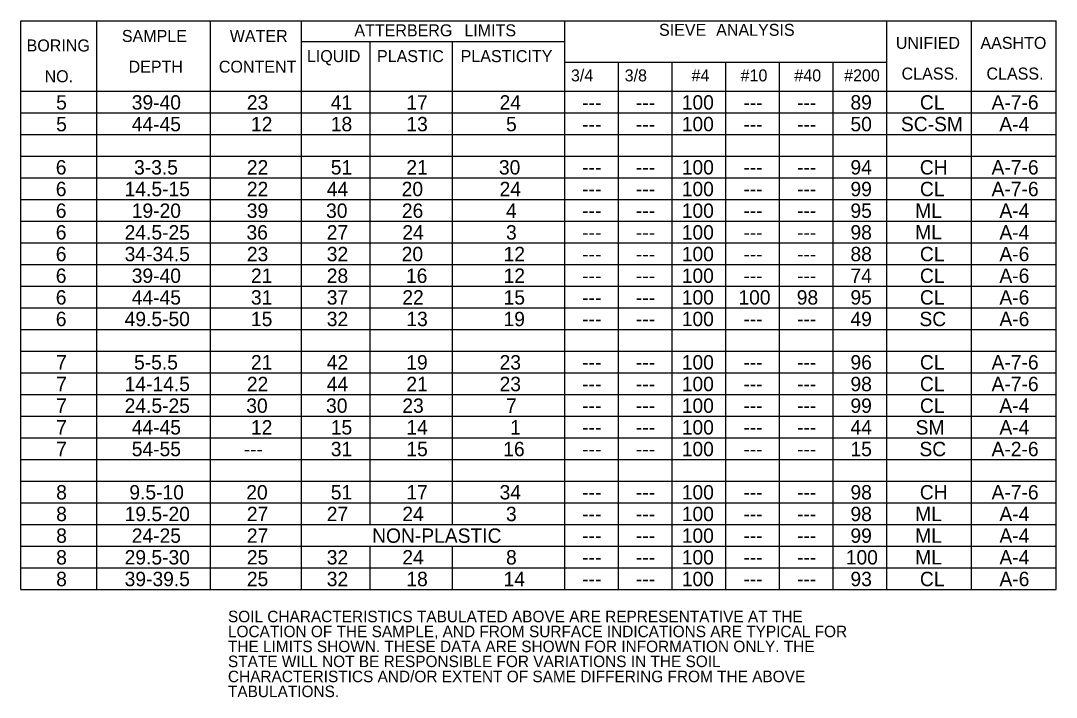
# Model space of a CAD drawing. Extents: x 1197542 to 1207464, y 185022 to 237324.
# Drawn here: x 1206798.9 to 1206906.8, y 185052.2 to 185122.8 of the extents above; entities that cross this region are included whole.
import ezdxf

# ---------------------------------------------------------------- set-up
doc = ezdxf.new("R2010")
doc.units = 0
doc.layers.add('R_No Plot', color=7, linetype='Continuous')

msp = doc.modelspace()

# ---------------------------------------------------------------- linework, layer by layer
at = {"layer": 'R_No Plot'}
for p, q in [((1206798.86, 185122.77), (1206798.86, 185122.77)), ((1206798.86, 185122.77), (1206906.83, 185122.77)), ((1206798.86, 185063.47), (1206798.86, 185122.77)), ((1206806.8, 185063.47), (1206806.8, 185122.77)), ((1206818.64, 185063.47), (1206818.64, 185122.77)), ((1206828.14, 185063.47), (1206828.14, 185122.77)), ((1206855.58, 185063.47), (1206855.58, 185122.77)), ((1206889.16, 185063.47), (1206889.16, 185122.77)), ((1206898, 185063.47), (1206898, 185122.77)), ((1206906.83, 185063.47), (1206906.83, 185122.77)), ((1206828.14, 185120.6), (1206855.58, 185120.6)), ((1206835.3, 185070.25), (1206835.3, 185120.6)), ((1206843.88, 185070.25), (1206843.88, 185120.6)), ((1206855.58, 185118.44), (1206889.16, 185118.44)), ((1206861.17, 185063.47), (1206861.17, 185118.44)), ((1206866.77, 185063.47), (1206866.77, 185118.44)), ((1206872.37, 185063.47), (1206872.37, 185118.44)), ((1206877.97, 185063.47), (1206877.97, 185118.44)), ((1206883.57, 185063.47), (1206883.57, 185118.44)), ((1206798.86, 185115.42), (1206906.83, 185115.42)), ((1206889.16, 185115.42), (1206906.83, 185115.42)), ((1206798.86, 185113.16), (1206906.83, 185113.16)), ((1206798.86, 185110.9), (1206906.83, 185110.9)), ((1206798.86, 185108.64), (1206906.83, 185108.64)), ((1206798.86, 185106.39), (1206906.83, 185106.39)), ((1206798.86, 185104.13), (1206906.83, 185104.13)), ((1206798.86, 185101.87), (1206906.83, 185101.87)), ((1206798.86, 185099.61), (1206906.83, 185099.61)), ((1206798.86, 185097.35), (1206906.83, 185097.35)), ((1206798.86, 185095.09), (1206906.83, 185095.09)), ((1206798.86, 185092.83), (1206906.83, 185092.83)), ((1206798.86, 185090.57), (1206906.83, 185090.57)), ((1206798.86, 185088.32), (1206906.83, 185088.32)), ((1206798.86, 185086.06), (1206906.83, 185086.06)), ((1206798.86, 185083.8), (1206906.83, 185083.8)), ((1206798.86, 185081.54), (1206906.83, 185081.54)), ((1206798.86, 185079.28), (1206906.83, 185079.28)), ((1206798.86, 185077.02), (1206906.83, 185077.02)), ((1206798.86, 185074.76), (1206906.83, 185074.76)), ((1206798.86, 185072.5), (1206906.83, 185072.5)), ((1206798.86, 185070.25), (1206906.83, 185070.25)), ((1206798.86, 185067.99), (1206906.83, 185067.99)), ((1206835.3, 185063.47), (1206835.3, 185067.99)), ((1206843.88, 185063.47), (1206843.88, 185067.99)), ((1206798.86, 185065.73), (1206906.83, 185065.73)), ((1206798.86, 185063.47), (1206906.83, 185063.47))]:
    msp.add_line(p, q, dxfattribs=at)

# ---------------------------------------------------------------- texts
for s, height, p in [('ATTERBERG', 1.25, (1206833.65, 185121.14)), ('LIMITS', 1.25, (1206845.12, 185121.14)), ('SIEVE', 1.25, (1206865.41, 185121.19)), ('ANALYSIS', 1.25, (1206871.37, 185121.19)), ('SAMPLE', 1.25, (1206809.41, 185120.55)), ('WATER', 1.25, (1206820.66, 185120.55)), ('BORING', 1.25, (1206799.48, 185119.56)), ('UNIFIED', 1.25, (1206890.1, 185119.83)), ('AASHTO', 1.25, (1206898.92, 185119.83)), ('LIQUID', 1.25, (1206828.7, 185118.45)), ('PLASTIC', 1.25, (1206836.01, 185118.45)), ('PLASTICITY', 1.25, (1206844.73, 185118.45)), ('DEPTH', 1.25, (1206810.11, 185117.35)), ('CONTENT', 1.25, (1206819.52, 185117.35)), ('CLASS.', 1.25, (1206890.7, 185116.63)), ('CLASS.', 1.25, (1206899.55, 185116.63)), ('NO.', 1.25, (1206801.35, 185116.35)), ('3/4', 1.25, (1206856.23, 185116.44)), ('3/8', 1.25, (1206861.83, 185116.44)), ('#4', 1.25, (1206868.8, 185116.44)), ('#10', 1.25, (1206873.92, 185116.44)), ('#40', 1.25, (1206879.52, 185116.44)), ('#200', 1.25, (1206884.71, 185116.44)), ('5', 1.5, (1206802.56, 185113.5)), ('39-40', 1.5, (1206810.44, 185113.5)), ('23', 1.5, (1206822.44, 185113.5)), ('41', 1.5, (1206831.19, 185113.5)), ('17', 1.5, (1206839.07, 185113.5)), ('24', 1.5, (1206848.79, 185113.5)), ('100', 1.5, (1206867.78, 185113.5)), ('89', 1.5, (1206885.37, 185113.5)), ('CL', 1.5, (1206892.61, 185113.5)), ('A-7-6', 1.5, (1206900.08, 185113.5)), ('---', 1.5, (1206857.4, 185113.5)), ('---', 1.5, (1206863, 185113.5)), ('---', 1.5, (1206874.2, 185113.5)), ('---', 1.5, (1206879.8, 185113.5)), ('5', 1.5, (1206802.56, 185111.24)), ('44-45', 1.5, (1206810.44, 185111.24)), ('12', 1.5, (1206822.87, 185111.24)), ('18', 1.5, (1206831.19, 185111.24)), ('13', 1.5, (1206839.07, 185111.24)), ('5', 1.5, (1206849.46, 185111.24)), ('100', 1.5, (1206867.78, 185111.24)), ('50', 1.5, (1206885.37, 185111.24)), ('SC-SM', 1.5, (1206890.63, 185111.24)), ('A-4', 1.5, (1206900.89, 185111.24)), ('---', 1.5, (1206857.4, 185111.24)), ('---', 1.5, (1206863, 185111.24)), ('---', 1.5, (1206874.2, 185111.24)), ('---', 1.5, (1206879.8, 185111.24)), ('6', 1.5, (1206802.52, 185106.73)), ('3-3.5', 1.5, (1206810.68, 185106.73)), ('22', 1.5, (1206822.44, 185106.73)), ('51', 1.5, (1206831.19, 185106.73)), ('21', 1.5, (1206839.07, 185106.73)), ('30', 1.5, (1206848.72, 185106.73)), ('100', 1.5, (1206867.78, 185106.73)), ('94', 1.5, (1206885.37, 185106.73)), ('CH', 1.5, (1206892.6, 185106.73)), ('A-7-6', 1.5, (1206900.08, 185106.73)), ('---', 1.5, (1206857.4, 185106.73)), ('---', 1.5, (1206863, 185106.73)), ('---', 1.5, (1206874.2, 185106.73)), ('---', 1.5, (1206879.8, 185106.73)), ('6', 1.5, (1206802.52, 185104.47)), ('14.5-15', 1.5, (1206809.7, 185104.47)), ('22', 1.5, (1206822.44, 185104.47)), ('44', 1.5, (1206830.77, 185104.47)), ('20', 1.5, (1206838.58, 185104.47)), ('24', 1.5, (1206848.79, 185104.47)), ('---', 1.5, (1206857.4, 185104.47)), ('---', 1.5, (1206863, 185104.47)), ('100', 1.5, (1206867.78, 185104.47)), ('---', 1.5, (1206874.2, 185104.47)), ('---', 1.5, (1206879.8, 185104.47)), ('99', 1.5, (1206885.37, 185104.47)), ('CL', 1.5, (1206892.61, 185104.47)), ('A-7-6', 1.5, (1206900.08, 185104.47)), ('6', 1.5, (1206802.52, 185102.21)), ('19-20', 1.5, (1206810.44, 185102.21)), ('39', 1.5, (1206822.43, 185102.21)), ('30', 1.5, (1206830.7, 185102.21)), ('26', 1.5, (1206838.6, 185102.21)), ('4', 1.5, (1206849.46, 185102.21)), ('---', 1.5, (1206857.4, 185102.21)), ('---', 1.5, (1206863, 185102.21)), ('100', 1.5, (1206867.78, 185102.21)), ('---', 1.5, (1206874.2, 185102.21)), ('---', 1.5, (1206879.8, 185102.21)), ('95', 1.5, (1206885.37, 185102.21)), ('ML', 1.5, (1206892.12, 185102.21)), ('A-4', 1.5, (1206900.9, 185102.21)), ('6', 1.5, (1206802.52, 185099.95)), ('24.5-25', 1.5, (1206809.7, 185099.95)), ('36', 1.5, (1206822.4, 185099.95)), ('27', 1.5, (1206830.77, 185099.95)), ('24', 1.5, (1206838.65, 185099.95)), ('3', 1.5, (1206849.46, 185099.95)), ('---', 1.5, (1206857.4, 185099.95)), ('---', 1.5, (1206863, 185099.95)), ('100', 1.5, (1206867.78, 185099.95)), ('---', 1.5, (1206874.2, 185099.95)), ('---', 1.5, (1206879.8, 185099.95)), ('98', 1.5, (1206885.37, 185099.95)), ('ML', 1.5, (1206892.12, 185099.97)), ('A-4', 1.5, (1206900.9, 185099.95)), ('6', 1.5, (1206802.52, 185097.69)), ('34-34.5', 1.5, (1206809.7, 185097.69)), ('23', 1.5, (1206822.44, 185097.69)), ('32', 1.5, (1206830.77, 185097.69)), ('20', 1.5, (1206838.58, 185097.69)), ('12', 1.5, (1206849.21, 185097.69)), ('100', 1.5, (1206867.78, 185097.69)), ('88', 1.5, (1206885.37, 185097.69)), ('CL', 1.5, (1206892.61, 185097.69)), ('A-6', 1.5, (1206900.9, 185097.69)), ('---', 1.5, (1206857.4, 185097.69)), ('---', 1.5, (1206863, 185097.69)), ('---', 1.5, (1206874.2, 185097.69)), ('---', 1.5, (1206879.8, 185097.69)), ('6', 1.5, (1206802.52, 185095.43)), ('39-40', 1.5, (1206810.44, 185095.43)), ('21', 1.5, (1206822.87, 185095.43)), ('28', 1.5, (1206830.77, 185095.43)), ('16', 1.5, (1206839.03, 185095.43)), ('12', 1.5, (1206849.21, 185095.43)), ('100', 1.5, (1206867.78, 185095.43)), ('74', 1.5, (1206885.37, 185095.43)), ('CL', 1.5, (1206892.61, 185095.43)), ('A-6', 1.5, (1206900.9, 185095.43)), ('---', 1.5, (1206857.4, 185095.43)), ('---', 1.5, (1206863, 185095.43)), ('---', 1.5, (1206874.2, 185095.43)), ('---', 1.5, (1206879.8, 185095.43)), ('6', 1.5, (1206802.52, 185093.17)), ('44-45', 1.5, (1206810.44, 185093.17)), ('31', 1.5, (1206822.87, 185093.17)), ('37', 1.5, (1206830.77, 185093.17)), ('22', 1.5, (1206838.65, 185093.17)), ('15', 1.5, (1206849.21, 185093.17)), ('100', 1.5, (1206867.78, 185093.17)), ('100', 1.5, (1206873.69, 185093.17)), ('98', 1.5, (1206879.77, 185093.17)), ('95', 1.5, (1206885.37, 185093.17)), ('CL', 1.5, (1206892.61, 185093.17)), ('A-6', 1.5, (1206900.9, 185093.17)), ('---', 1.5, (1206857.4, 185093.17)), ('---', 1.5, (1206863, 185093.17)), ('6', 1.5, (1206802.52, 185090.92)), ('49.5-50', 1.5, (1206809.7, 185090.92)), ('15', 1.5, (1206822.87, 185090.92)), ('32', 1.5, (1206830.77, 185090.92)), ('13', 1.5, (1206839.07, 185090.92)), ('19', 1.5, (1206849.2, 185090.92)), ('100', 1.5, (1206867.78, 185090.92)), ('49', 1.5, (1206885.37, 185090.92)), ('SC', 1.5, (1206892.56, 185090.92)), ('A-6', 1.5, (1206900.9, 185090.92)), ('---', 1.5, (1206857.4, 185090.92)), ('---', 1.5, (1206863, 185090.92)), ('---', 1.5, (1206874.2, 185090.92)), ('---', 1.5, (1206879.8, 185090.92)), ('7', 1.5, (1206802.56, 185086.4)), ('5-5.5', 1.5, (1206810.68, 185086.4)), ('21', 1.5, (1206822.87, 185086.4)), ('42', 1.5, (1206830.77, 185086.4)), ('19', 1.5, (1206839.06, 185086.4)), ('23', 1.5, (1206848.79, 185086.4)), ('100', 1.5, (1206867.78, 185086.4)), ('96', 1.5, (1206885.37, 185086.4)), ('CL', 1.5, (1206892.61, 185086.4)), ('A-7-6', 1.5, (1206900.08, 185086.4)), ('---', 1.5, (1206857.4, 185086.4)), ('---', 1.5, (1206863, 185086.4)), ('---', 1.5, (1206874.2, 185086.4)), ('---', 1.5, (1206879.8, 185086.4)), ('7', 1.5, (1206802.56, 185084.14)), ('14-14.5', 1.5, (1206809.7, 185084.14)), ('22', 1.5, (1206822.44, 185084.14)), ('44', 1.5, (1206830.77, 185084.14)), ('21', 1.5, (1206839.07, 185084.14)), ('23', 1.5, (1206848.79, 185084.14)), ('100', 1.5, (1206867.78, 185084.14)), ('98', 1.5, (1206885.37, 185084.14)), ('CL', 1.5, (1206892.61, 185084.14)), ('A-7-6', 1.5, (1206900.08, 185084.14)), ('---', 1.5, (1206857.4, 185084.14)), ('---', 1.5, (1206863, 185084.14)), ('---', 1.5, (1206874.2, 185084.14)), ('---', 1.5, (1206879.8, 185084.14)), ('7', 1.5, (1206802.56, 185081.88)), ('24.5-25', 1.5, (1206809.7, 185081.88)), ('30', 1.5, (1206822.38, 185081.88)), ('30', 1.5, (1206830.7, 185081.88)), ('23', 1.5, (1206838.65, 185081.88)), ('7', 1.5, (1206849.46, 185081.88)), ('100', 1.5, (1206867.78, 185081.88)), ('99', 1.5, (1206885.37, 185081.88)), ('CL', 1.5, (1206892.61, 185081.88)), ('A-4', 1.5, (1206900.9, 185081.88)), ('---', 1.5, (1206857.4, 185081.88)), ('---', 1.5, (1206863, 185081.88)), ('---', 1.5, (1206874.2, 185081.88)), ('---', 1.5, (1206879.8, 185081.88)), ('7', 1.5, (1206802.56, 185079.62)), ('44-45', 1.5, (1206810.44, 185079.62)), ('12', 1.5, (1206822.87, 185079.62)), ('15', 1.5, (1206831.19, 185079.62)), ('14', 1.5, (1206839.07, 185079.62)), ('1', 1.5, (1206849.88, 185079.62)), ('---', 1.5, (1206857.4, 185079.62)), ('---', 1.5, (1206863, 185079.62)), ('100', 1.5, (1206867.78, 185079.62)), ('---', 1.5, (1206874.2, 185079.62)), ('---', 1.5, (1206879.8, 185079.62)), ('44', 1.5, (1206885.37, 185079.62)), ('SM', 1.5, (1206892.16, 185079.62)), ('A-4', 1.5, (1206900.9, 185079.62)), ('7', 1.5, (1206802.56, 185077.36)), ('54-55', 1.5, (1206810.44, 185077.36)), ('---', 1.5, (1206822.11, 185077.36)), ('31', 1.5, (1206831.19, 185077.36)), ('15', 1.5, (1206839.07, 185077.36)), ('16', 1.5, (1206849.17, 185077.36)), ('---', 1.5, (1206857.4, 185077.36)), ('---', 1.5, (1206863, 185077.36)), ('100', 1.5, (1206867.78, 185077.36)), ('---', 1.5, (1206874.2, 185077.36)), ('---', 1.5, (1206879.8, 185077.36)), ('15', 1.5, (1206885.37, 185077.36)), ('SC', 1.5, (1206892.56, 185077.36)), ('A-2-6', 1.5, (1206900.08, 185077.36)), ('8', 1.5, (1206802.56, 185072.85)), ('9.5-10', 1.5, (1206810.19, 185072.85)), ('20', 1.5, (1206822.38, 185072.85)), ('51', 1.5, (1206831.19, 185072.85)), ('17', 1.5, (1206839.07, 185072.85)), ('34', 1.5, (1206848.79, 185072.85)), ('100', 1.5, (1206867.78, 185072.85)), ('98', 1.5, (1206885.37, 185072.85)), ('CH', 1.5, (1206892.6, 185072.85)), ('A-7-6', 1.5, (1206900.08, 185072.85)), ('---', 1.5, (1206857.4, 185072.85)), ('---', 1.5, (1206863, 185072.85)), ('---', 1.5, (1206874.2, 185072.85)), ('---', 1.5, (1206879.8, 185072.85)), ('8', 1.5, (1206802.56, 185070.59)), ('19.5-20', 1.5, (1206809.7, 185070.59)), ('27', 1.5, (1206822.44, 185070.59)), ('27', 1.5, (1206830.77, 185070.59)), ('24', 1.5, (1206838.65, 185070.59)), ('3', 1.5, (1206849.46, 185070.59)), ('100', 1.5, (1206867.78, 185070.59)), ('98', 1.5, (1206885.37, 185070.59)), ('ML', 1.5, (1206892.12, 185070.59)), ('A-4', 1.5, (1206900.9, 185070.59)), ('---', 1.5, (1206857.4, 185070.59)), ('---', 1.5, (1206863, 185070.59)), ('---', 1.5, (1206874.2, 185070.59)), ('---', 1.5, (1206879.8, 185070.59)), ('8', 1.5, (1206802.56, 185068.33)), ('24-25', 1.5, (1206810.44, 185068.33)), ('27', 1.5, (1206822.44, 185068.33)), ('NON-PLASTIC', 1.5, (1206835.5, 185068.33)), ('100', 1.5, (1206867.78, 185068.33)), ('99', 1.5, (1206885.37, 185068.33)), ('ML', 1.5, (1206892.12, 185068.33)), ('A-4', 1.5, (1206900.9, 185068.33)), ('---', 1.5, (1206857.4, 185068.33)), ('---', 1.5, (1206863, 185068.33)), ('---', 1.5, (1206874.2, 185068.33)), ('---', 1.5, (1206879.8, 185068.33)), ('8', 1.5, (1206802.56, 185066.07)), ('29.5-30', 1.5, (1206809.7, 185066.07)), ('25', 1.5, (1206822.44, 185066.07)), ('32', 1.5, (1206830.77, 185066.07)), ('24', 1.5, (1206838.65, 185066.07)), ('8', 1.5, (1206849.46, 185066.07)), ('100', 1.5, (1206867.78, 185066.07)), ('100', 1.5, (1206884.88, 185066.07)), ('ML', 1.5, (1206892.12, 185066.07)), ('A-4', 1.5, (1206900.9, 185066.07)), ('---', 1.5, (1206857.4, 185066.07)), ('---', 1.5, (1206863, 185066.07)), ('---', 1.5, (1206874.2, 185066.07)), ('---', 1.5, (1206879.8, 185066.07)), ('8', 1.5, (1206802.56, 185063.81)), ('39-39.5', 1.5, (1206809.7, 185063.81)), ('25', 1.5, (1206822.44, 185063.81)), ('32', 1.5, (1206830.77, 185063.81)), ('18', 1.5, (1206839.07, 185063.81)), ('14', 1.5, (1206849.21, 185063.81)), ('100', 1.5, (1206867.78, 185063.81)), ('93', 1.5, (1206885.37, 185063.81)), ('CL', 1.5, (1206892.61, 185063.81)), ('A-6', 1.5, (1206900.9, 185063.81)), ('---', 1.5, (1206857.4, 185063.81)), ('---', 1.5, (1206863, 185063.81)), ('---', 1.5, (1206874.2, 185063.81)), ('---', 1.5, (1206879.8, 185063.81)), ('SOIL CHARACTERISTICS TABULATED ABOVE ARE REPRESENTATIVE AT THE ', 1.2, (1206820.47, 185060.05)), ('LOCATION OF THE SAMPLE, AND FROM SURFACE INDICATIONS ARE TYPICAL FOR ', 1.2, (1206820.47, 185058.49)), ('THE LIMITS SHOWN. THESE DATA ARE SHOWN FOR INFORMATION ONLY. THE ', 1.2, (1206820.47, 185056.93)), ('STATE WILL NOT BE RESPONSIBLE FOR VARIATIONS IN THE SOIL ', 1.2, (1206820.47, 185055.37)), ('CHARACTERISTICS AND/OR EXTENT OF SAME DIFFERING FROM THE ABOVE ', 1.2, (1206820.47, 185053.8)), ('TABULATIONS.', 1.2, (1206820.47, 185052.24))]:
    msp.add_text(s, height=height, dxfattribs=at).set_placement(p)

doc.saveas('drawing.dxf')
